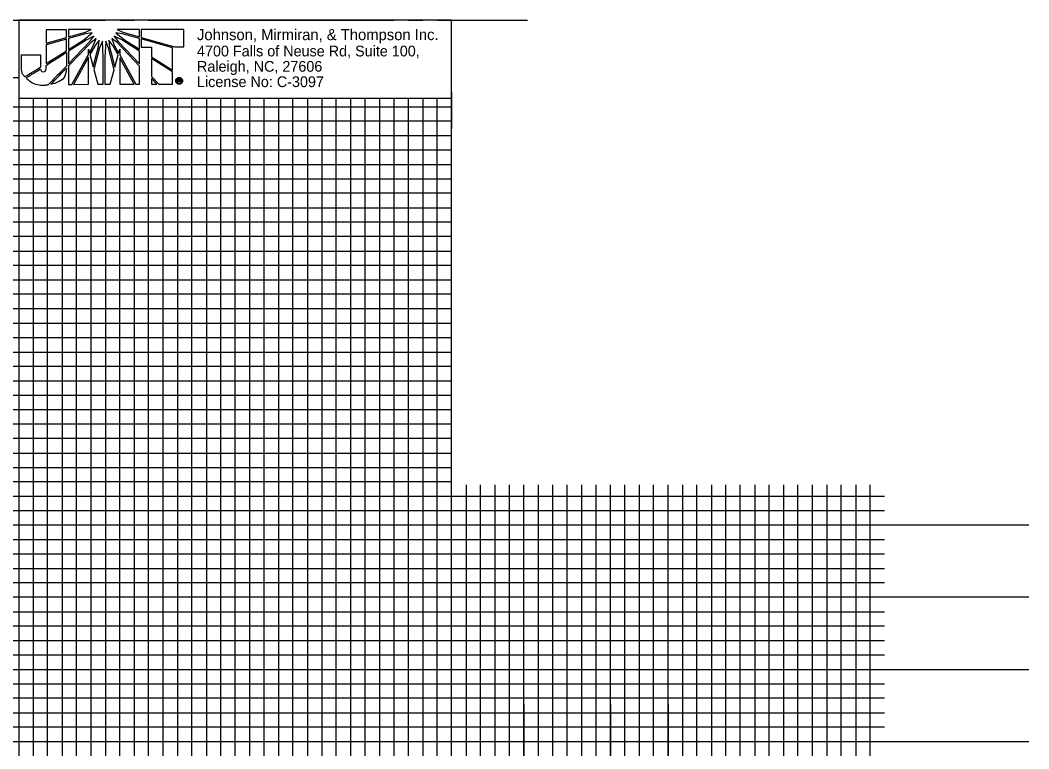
# Model space of a CAD drawing. Extents: x 1648435 to 1651603, y 802691 to 845762.
# Drawn here: x 1651253.8 to 1651603.3, y 845509.5 to 845762 of the extents above; entities that cross this region are included whole.
import ezdxf

# ---------------------------------------------------------------- set-up
doc = ezdxf.new("R2010")
doc.units = 0
for name, color, linetype in [('Prop Dimension Text', 7, 'Continuous'), ('Sheet Plan CELL', 7, 'Continuous'), ('Sheet Profile Grid Major CELL', 7, 'Continuous'), ('Sheet Profile Grid Middle CELL', 7, 'Continuous'), ('Sheet Profile Grid Minor CELL', 7, 'Continuous')]:
    doc.layers.add(name, color=color, linetype=linetype)

msp = doc.modelspace()

# ---------------------------------------------------------------- linework, layer by layer
at = {"layer": 'Prop Dimension Text'}
for p, q in [((1651269.85, 845758.65), (1651262.83, 845758.65)), ((1651262.83, 845758.65), (1651262.84, 845753.99)), ((1651269.85, 845755.94), (1651269.85, 845758.65)), ((1651278.48, 845758.7), (1651270.58, 845758.69)), ((1651270.58, 845758.69), (1651270.58, 845756.18)), ((1651270.58, 845756.18), (1651276.47, 845757.8)), ((1651276.47, 845757.26), (1651270.58, 845755.63)), ((1651275.85, 845755.17), (1651278.76, 845757.54)), ((1651276.47, 845757.8), (1651278.48, 845758.7)), ((1651278.76, 845757.54), (1651276.47, 845757.26)), ((1651279.34, 845756.45), (1651276.66, 845755.09)), ((1651277.99, 845754.55), (1651279.34, 845756.45)), ((1651286.41, 845756.46), (1651287.77, 845754.52)), ((1651289.12, 845755.1), (1651286.41, 845756.46)), ((1651287.03, 845757.55), (1651289.97, 845755.14)), ((1651289.19, 845757.27), (1651287.03, 845757.55)), ((1651295.2, 845758.68), (1651287.42, 845758.7)), ((1651287.42, 845758.7), (1651289.39, 845757.78)), ((1651295.2, 845755.62), (1651289.19, 845757.27)), ((1651289.39, 845757.78), (1651295.2, 845756.15)), ((1651295.2, 845756.15), (1651295.2, 845758.68)), ((1651310.5, 845758.73), (1651295.74, 845758.71)), ((1651295.74, 845758.71), (1651295.75, 845756)), ((1651310.5, 845752.68), (1651310.5, 845758.73)), ((1651262.84, 845753.99), (1651269.85, 845755.94)), ((1651269.86, 845755.43), (1651262.84, 845753.46)), ((1651262.84, 845753.46), (1651262.85, 845746.92)), ((1651269.86, 845751.37), (1651269.86, 845755.43)), ((1651270.58, 845755.63), (1651270.59, 845751.83)), ((1651270.59, 845751.83), (1651275.85, 845755.17)), ((1651276.66, 845755.09), (1651270.59, 845751.22)), ((1651270.59, 845746.84), (1651277.99, 845754.55)), ((1651278.29, 845754.17), (1651270.59, 845746.1)), ((1651277.83, 845750.68), (1651279.29, 845753.36)), ((1651279.77, 845753.2), (1651278.02, 845750.02)), ((1651280.15, 845755.61), (1651278.29, 845754.17)), ((1651279.29, 845753.36), (1651280.15, 845755.61)), ((1651281.16, 845754.98), (1651279.77, 845753.2)), ((1651280.96, 845752.82), (1651281.16, 845754.98)), ((1651282.32, 845754.67), (1651281.36, 845752.42)), ((1651282.62, 845749.13), (1651282.32, 845754.67)), ((1651283.47, 845754.67), (1651283.12, 845749.14)), ((1651284.4, 845752.43), (1651283.47, 845754.67)), ((1651284.6, 845754.98), (1651284.83, 845752.74)), ((1651285.95, 845753.2), (1651284.6, 845754.98)), ((1651285.59, 845755.61), (1651286.45, 845753.36)), ((1651287.46, 845754.18), (1651285.59, 845755.61)), ((1651287.77, 845749.92), (1651285.95, 845753.2)), ((1651286.45, 845753.36), (1651287.96, 845750.58)), ((1651295.17, 845746.05), (1651287.46, 845754.18)), ((1651287.77, 845754.52), (1651295.17, 845746.78)), ((1651295.16, 845751.28), (1651289.12, 845755.1)), ((1651289.97, 845755.14), (1651295.16, 845751.9)), ((1651295.16, 845751.9), (1651295.2, 845755.62)), ((1651295.75, 845756), (1651295.75, 845755.92)), ((1651295.75, 845755.92), (1651307.37, 845752.68)), ((1651295.75, 845755.5), (1651295.75, 845755.46)), ((1651306.62, 845752.41), (1651295.75, 845755.5)), ((1651295.75, 845755.46), (1651295.75, 845752.63)), ((1651262.85, 845746.92), (1651269.86, 845751.37)), ((1651270.59, 845751.22), (1651270.59, 845746.84)), ((1651271.76, 845739.73), (1651277.48, 845750.1)), ((1651277.48, 845750.1), (1651277.48, 845751.96)), ((1651277.48, 845751.96), (1651277.83, 845750.68)), ((1651278.02, 845750.02), (1651279.15, 845745.81)), ((1651279.15, 845745.81), (1651280.96, 845752.82)), ((1651281.36, 845752.42), (1651279.38, 845744.84)), ((1651286.42, 845744.73), (1651284.4, 845752.43)), ((1651284.83, 845752.74), (1651286.66, 845745.65)), ((1651286.66, 845745.65), (1651287.77, 845749.92)), ((1651287.96, 845750.58), (1651288.32, 845751.97)), ((1651288.32, 845751.97), (1651288.32, 845749.92)), ((1651288.32, 845749.92), (1651293.93, 845739.75)), ((1651295.17, 845746.78), (1651295.16, 845751.28)), ((1651295.75, 845752.63), (1651299.35, 845752.64)), ((1651299.35, 845752.64), (1651299.36, 845749.27)), ((1651306.63, 845744.66), (1651306.62, 845752.41)), ((1651307.37, 845752.68), (1651310.5, 845752.68)), ((1651270.59, 845746.1), (1651270.6, 845739.73)), ((1651277.48, 845749.09), (1651272.3, 845739.73)), ((1651277.54, 845739.74), (1651277.48, 845749.09)), ((1651282.63, 845739.78), (1651282.62, 845749.13)), ((1651283.12, 845749.14), (1651283.13, 845739.78)), ((1651293.35, 845739.79), (1651288.32, 845748.91)), ((1651288.32, 845748.91), (1651288.33, 845739.78)), ((1651295.17, 845739.76), (1651295.17, 845746.05)), ((1651299.36, 845749.27), (1651306.63, 845744.66)), ((1651299.36, 845748.69), (1651299.36, 845742.41)), ((1651306.63, 845744.12), (1651299.36, 845748.69)), ((1651279.38, 845744.84), (1651280.71, 845739.78)), ((1651285.07, 845739.78), (1651286.42, 845744.73)), ((1651299.36, 845742.41), (1651301.88, 845739.76)), ((1651306.64, 845739.77), (1651306.63, 845744.12)), ((1651270.6, 845739.73), (1651271.76, 845739.73)), ((1651272.3, 845739.73), (1651277.54, 845739.74)), ((1651280.71, 845739.78), (1651282.63, 845739.78)), ((1651283.13, 845739.78), (1651285.07, 845739.78)), ((1651288.33, 845739.78), (1651293.35, 845739.79)), ((1651293.93, 845739.75), (1651295.17, 845739.76)), ((1651301.18, 845739.76), (1651299.36, 845741.73)), ((1651299.36, 845741.73), (1651299.36, 845739.76)), ((1651299.36, 845739.76), (1651301.18, 845739.76)), ((1651301.88, 845739.76), (1651306.64, 845739.77)), ((1651308.48, 845740.43), (1651308.48, 845741.5)), ((1651308.48, 845741.5), (1651308.92, 845741.5)), ((1651308.73, 845740.43), (1651308.48, 845740.43)), ((1651308.92, 845741.3), (1651308.73, 845741.3)), ((1651308.73, 845741.3), (1651308.73, 845741.04)), ((1651308.73, 845741.04), (1651308.92, 845741.05)), ((1651308.92, 845740.85), (1651308.73, 845740.85)), ((1651308.73, 845740.85), (1651308.73, 845740.43)), ((1651308.92, 845742.14), (1651308.92, 845741.91)), ((1651308.92, 845741.91), (1651308.92, 845742.14)), ((1651308.92, 845741.5), (1651308.92, 845741.3)), ((1651308.92, 845741.3), (1651308.92, 845741.5)), ((1651308.92, 845741.5), (1651308.99, 845741.5)), ((1651308.95, 845741.3), (1651308.92, 845741.3)), ((1651308.92, 845741.05), (1651308.92, 845740.85)), ((1651308.92, 845740.85), (1651308.92, 845741.05)), ((1651308.92, 845741.05), (1651308.93, 845741.05)), ((1651308.93, 845740.85), (1651308.92, 845740.85)), ((1651308.92, 845740.01), (1651308.92, 845739.78)), ((1651308.92, 845739.78), (1651308.92, 845740.01)), ((1651308.92, 845740.01), (1651308.93, 845740.01)), ((1651308.93, 845739.78), (1651308.92, 845739.78))]:
    msp.add_line(p, q, dxfattribs=at)
msp.add_lwpolyline([(1651253.34, 845734.91), (1651403.3, 845734.91), (1651403.3, 845761.97), (1651253.34, 845761.97)], close=True, dxfattribs=at)
for points in [[(1651262.84, 845753.99), (1651269.85, 845755.94), (1651269.85, 845758.65), (1651262.83, 845758.65), (1651262.84, 845753.99)], [(1651276.47, 845757.8), (1651278.48, 845758.7), (1651270.58, 845758.69), (1651270.58, 845756.18), (1651276.47, 845757.8)], [(1651270.58, 845755.63), (1651270.59, 845751.83), (1651275.85, 845755.17), (1651278.76, 845757.54), (1651276.47, 845757.26), (1651270.58, 845755.63)], [(1651270.59, 845751.22), (1651270.59, 845746.84), (1651277.99, 845754.55), (1651279.34, 845756.45), (1651276.66, 845755.09), (1651270.59, 845751.22)], [(1651286.41, 845756.46), (1651287.77, 845754.52), (1651295.17, 845746.78), (1651295.16, 845751.28), (1651289.12, 845755.1), (1651286.41, 845756.46)], [(1651287.03, 845757.55), (1651289.97, 845755.14), (1651295.16, 845751.9), (1651295.2, 845755.62), (1651289.19, 845757.27), (1651287.03, 845757.55)], [(1651289.39, 845757.78), (1651295.2, 845756.15), (1651295.2, 845758.68), (1651287.42, 845758.7), (1651289.39, 845757.78)], [(1651310.5, 845758.73), (1651295.74, 845758.71), (1651295.75, 845756), (1651295.75, 845755.92), (1651307.37, 845752.68), (1651310.5, 845752.68), (1651310.5, 845758.73)], [(1651262.85, 845746.92), (1651269.86, 845751.37), (1651269.86, 845755.43), (1651262.84, 845753.46), (1651262.85, 845746.92)], [(1651280.15, 845755.61), (1651278.29, 845754.17), (1651270.59, 845746.1), (1651270.6, 845739.73), (1651271.76, 845739.73), (1651277.48, 845750.1), (1651277.48, 845751.96), (1651277.83, 845750.68), (1651279.29, 845753.36), (1651280.15, 845755.61)], [(1651281.16, 845754.98), (1651279.77, 845753.2), (1651278.02, 845750.02), (1651279.15, 845745.81), (1651280.96, 845752.82), (1651281.16, 845754.98)], [(1651281.36, 845752.42), (1651279.38, 845744.84), (1651280.71, 845739.78), (1651282.63, 845739.78), (1651282.62, 845749.13), (1651282.32, 845754.67), (1651281.36, 845752.42)], [(1651283.47, 845754.67), (1651283.12, 845749.14), (1651283.13, 845739.78), (1651285.07, 845739.78), (1651286.42, 845744.73), (1651284.4, 845752.43), (1651283.47, 845754.67)], [(1651284.6, 845754.98), (1651284.83, 845752.74), (1651286.66, 845745.65), (1651287.77, 845749.92), (1651285.95, 845753.2), (1651284.6, 845754.98)], [(1651285.59, 845755.61), (1651286.45, 845753.36), (1651287.96, 845750.58), (1651288.32, 845751.97), (1651288.32, 845749.92), (1651293.93, 845739.75), (1651295.17, 845739.76), (1651295.17, 845746.05), (1651287.46, 845754.18), (1651285.59, 845755.61)], [(1651295.75, 845755.5), (1651295.75, 845755.46), (1651295.75, 845752.63), (1651299.35, 845752.64), (1651299.36, 845749.27), (1651306.63, 845744.66), (1651306.62, 845752.41), (1651295.75, 845755.5)], [(1651272.3, 845739.73), (1651277.54, 845739.74), (1651277.48, 845749.09), (1651272.3, 845739.73)], [(1651288.33, 845739.78), (1651293.35, 845739.79), (1651288.32, 845748.91), (1651288.33, 845739.78)], [(1651299.36, 845748.69), (1651299.36, 845742.41), (1651301.88, 845739.76), (1651306.64, 845739.77), (1651306.63, 845744.12), (1651299.36, 845748.69), (1651299.36, 845748.69)], [(1651299.36, 845739.76), (1651299.36, 845739.76), (1651301.18, 845739.76), (1651299.36, 845741.73), (1651299.36, 845739.76)], [(1651309.39, 845740.68), (1651309.39, 845740.63), (1651309.4, 845740.59), (1651309.4, 845740.55), (1651309.43, 845740.43), (1651309.21, 845740.43)]]:
    msp.add_lwpolyline(points, dxfattribs=at)
for points, degree in [([(1651260.83, 845749.92), (1651260.83, 845749.92), (1651254.33, 845749.92), (1651254.33, 845749.92), (1651254.33, 845749.92), (1651254.34, 845745.85), (1651254.34, 845745.85), (1651254.34, 845745.85), (1651254.34, 845745.43), (1651254.34, 845745.43), (1651254.34, 845744.15), (1651254.76, 845743.14), (1651255.5, 845742.3), (1651255.5, 845742.3), (1651260.83, 845745.55), (1651260.83, 845745.63), (1651260.83, 845745.63), (1651260.83, 845749.92), (1651260.83, 845749.92)], 3), ([(1651261.84, 845744.08), (1651261.42, 845744.08), (1651261.07, 845744.31), (1651260.91, 845745.08), (1651260.91, 845745.08), (1651255.88, 845741.96), (1651255.88, 845741.96), (1651257.43, 845740.33), (1651259.91, 845739.36), (1651262.01, 845739.36), (1651262.55, 845739.37), (1651262.97, 845739.41), (1651263.55, 845739.53), (1651263.55, 845739.53), (1651269.86, 845746.07), (1651269.86, 845746.07), (1651269.86, 845746.07), (1651269.86, 845750.79), (1651269.86, 845750.79), (1651269.86, 845750.79), (1651262.85, 845746.32), (1651262.85, 845746.32), (1651262.85, 845744.55), (1651262.42, 845744.08), (1651261.84, 845744.08)], 3), ([(1651261.84, 845744.08), (1651261.42, 845744.08), (1651261.07, 845744.31), (1651260.91, 845745.08), (1651260.91, 845745.08), (1651255.88, 845741.96), (1651255.88, 845741.96), (1651257.43, 845740.33), (1651259.91, 845739.36), (1651262.01, 845739.36), (1651262.55, 845739.37), (1651262.97, 845739.41), (1651263.55, 845739.53), (1651263.55, 845739.53), (1651269.86, 845746.07), (1651269.86, 845746.07), (1651269.86, 845746.07), (1651269.86, 845750.79), (1651269.86, 845750.79), (1651269.86, 845750.79), (1651262.85, 845746.32), (1651262.85, 845746.32), (1651262.85, 845744.55), (1651262.42, 845744.08), (1651261.84, 845744.08)], 3), ([(1651269.86, 845745.32), (1651269.86, 845745.32), (1651264.4, 845739.68), (1651264.4, 845739.68), (1651267.08, 845740.34), (1651269.74, 845742.12), (1651269.86, 845745.32)], 3), ([(1651308.92, 845739.78), (1651308.6, 845739.78), (1651308.32, 845739.89), (1651308.08, 845740.13), (1651307.85, 845740.35), (1651307.73, 845740.63), (1651307.73, 845740.97), (1651307.73, 845741.3), (1651307.85, 845741.58), (1651308.08, 845741.8), (1651308.32, 845742.02), (1651308.59, 845742.14), (1651308.92, 845742.14)], 3), ([(1651308.92, 845741.91), (1651308.66, 845741.91), (1651308.43, 845741.82), (1651308.25, 845741.65), (1651308.06, 845741.46), (1651307.97, 845741.23), (1651307.97, 845740.97), (1651307.97, 845740.7), (1651308.06, 845740.47), (1651308.25, 845740.28), (1651308.44, 845740.1), (1651308.66, 845740.01), (1651308.92, 845740.01)], 3), ([(1651308.92, 845742.14), (1651309.25, 845742.14), (1651309.54, 845742.02), (1651309.77, 845741.8), (1651310, 845741.58), (1651310.12, 845741.3), (1651310.12, 845740.97)], 3), ([(1651308.93, 845740.01), (1651309.2, 845740.01), (1651309.42, 845740.1), (1651309.61, 845740.29), (1651309.79, 845740.47), (1651309.89, 845740.7), (1651309.89, 845740.97), (1651309.89, 845741.23), (1651309.79, 845741.47), (1651309.6, 845741.65), (1651309.42, 845741.83), (1651309.19, 845741.91), (1651308.92, 845741.91)], 3), ([(1651308.93, 845741.05), (1651309.09, 845741.05), (1651309.17, 845741.09), (1651309.17, 845741.18), (1651309.17, 845741.26), (1651309.1, 845741.3), (1651308.95, 845741.3)], 3), ([(1651310.12, 845740.97), (1651310.12, 845740.64), (1651310.01, 845740.35), (1651309.78, 845740.12), (1651309.55, 845739.89), (1651309.26, 845739.78), (1651308.93, 845739.78)], 3), ([(1651309.12, 845740.81), (1651309.09, 845740.83), (1651309.03, 845740.85), (1651308.93, 845740.85)], 2), ([(1651308.99, 845741.5), (1651309.26, 845741.5), (1651309.4, 845741.4), (1651309.4, 845741.18), (1651309.4, 845741.08), (1651309.36, 845741.01), (1651309.27, 845740.95)], 3), ([(1651309.21, 845740.43), (1651309.18, 845740.49), (1651309.16, 845740.55), (1651309.16, 845740.63), (1651309.16, 845740.72), (1651309.15, 845740.78), (1651309.12, 845740.81)], 3), ([(1651309.27, 845740.95), (1651309.34, 845740.91), (1651309.38, 845740.82), (1651309.39, 845740.68)], 2)]:
    msp.add_open_spline(points, degree=degree, dxfattribs=at)
at = {"layer": 'Sheet Plan CELL'}
msp.add_line((1651403.3, 845736.88), (1651403.3, 845724.39), dxfattribs=at)
msp.add_line((1651403.3, 845736.88), (1651403.3, 845724.39), dxfattribs=at)
at = {"layer": 'Sheet Profile Grid Major CELL'}
for points in [[(1650803.35, 845761.97), (1650853.35, 845761.97), (1650853.35, 845261.97), (1650903.35, 845261.97), (1650903.35, 845761.97), (1650953.35, 845761.97), (1650953.35, 845261.97), (1651003.35, 845261.97), (1651003.35, 845761.97), (1651053.35, 845761.97), (1651053.35, 845261.97), (1651103.35, 845261.97), (1651103.35, 845761.97), (1651153.35, 845761.97), (1651153.35, 845261.97), (1651203.35, 845261.97), (1651203.35, 845761.97), (1651253.35, 845761.97), (1651253.35, 845261.97), (1651303.35, 845261.97), (1651303.35, 845734.91)], [(1651303.35, 845761.97), (1651353.35, 845761.97)], [(1651353.35, 845734.91), (1651353.35, 845261.97), (1651403.35, 845261.97), (1651403.35, 845761.97), (1651429.65, 845761.97)], [(1650103.35, 845711.97), (1651403.35, 845711.97)], [(1651403.35, 845661.97), (1650103.35, 845661.97), (1650103.35, 845611.97), (1651403.35, 845611.97)], [(1651453.35, 845600.92), (1651453.35, 845261.97), (1651503.35, 845261.97), (1651503.35, 845261.97), (1651503.35, 845600.92)], [(1651603.35, 845561.97), (1650103.35, 845561.97), (1650103.35, 845511.97), (1651603.35, 845511.97)]]:
    msp.add_lwpolyline(points, dxfattribs=at)
at = {"layer": 'Sheet Profile Grid Middle CELL'}
for points in [[(1650828.35, 845761.97), (1650878.35, 845761.97), (1650878.35, 845261.97), (1650928.35, 845261.97), (1650928.35, 845761.97), (1650978.35, 845761.97), (1650978.35, 845261.97), (1651028.35, 845261.97), (1651028.35, 845761.97), (1651078.35, 845761.97), (1651078.35, 845261.97), (1651128.35, 845261.97), (1651128.35, 845761.97), (1651178.35, 845761.97), (1651178.35, 845261.97), (1651228.35, 845261.97), (1651228.35, 845761.97), (1651278.35, 845761.97)], [(1651328.35, 845761.97), (1651378.35, 845761.97)], [(1651278.35, 845734.91), (1651278.35, 845261.97), (1651328.35, 845261.97), (1651328.35, 845734.91)], [(1651378.35, 845734.91), (1651378.35, 845261.97), (1651428.35, 845261.97), (1651428.35, 845600.92)], [(1651403.35, 845686.97), (1650103.35, 845686.97), (1650103.35, 845636.97), (1651403.35, 845636.97)], [(1651428.35, 845524.77), (1651428.35, 845261.97), (1651478.35, 845261.97), (1651478.35, 845600.92)], [(1651478.35, 845524.77), (1651478.35, 845261.97), (1651528.35, 845261.97), (1651528.35, 845600.92)], [(1651603.35, 845586.97), (1650103.35, 845586.97), (1650103.35, 845536.97), (1651428.35, 845536.97)], [(1651428.35, 845536.97), (1651603.35, 845536.97)], [(1651428.35, 845536.97), (1651603.35, 845536.97)]]:
    msp.add_lwpolyline(points, dxfattribs=at)
at = {"layer": 'Sheet Profile Grid Minor CELL'}
for p, q in [((1651403.3, 845756.97), (1651403.35, 845756.97)), ((1651403.35, 845751.97), (1651403.3, 845751.97)), ((1651403.3, 845746.97), (1651403.35, 845746.97)), ((1651403.3, 845626.97), (1650153.35, 845626.97)), ((1651403.35, 845621.97), (1650153.35, 845621.97)), ((1651403.35, 845616.97), (1650153.35, 845616.97)), ((1650153.35, 845606.97), (1651403.35, 845606.97)), ((1651403.35, 845601.97), (1650153.35, 845601.97)), ((1650153.35, 845596.97), (1651553.35, 845596.97)), ((1651553.35, 845576.97), (1650153.35, 845576.97)), ((1650153.35, 845571.97), (1651553.35, 845571.97)), ((1651553.35, 845551.97), (1650153.35, 845551.97)), ((1650153.35, 845546.97), (1651553.35, 845546.97)), ((1651553.35, 845526.97), (1650153.35, 845526.97)), ((1650153.35, 845521.97), (1651553.35, 845521.97)), ((1651553.35, 845516.97), (1650153.35, 845516.97))]:
    msp.add_line(p, q, dxfattribs=at)
for points in [[(1651248.35, 845761.97), (1651258.35, 845761.97)], [(1651263.35, 845761.97), (1651268.35, 845761.97)], [(1651273.35, 845761.97), (1651283.35, 845761.97)], [(1651288.35, 845761.97), (1651293.35, 845761.97)], [(1651298.35, 845761.97), (1651308.35, 845761.97)], [(1651313.35, 845761.97), (1651318.35, 845761.97)], [(1651323.35, 845761.97), (1651333.35, 845761.97)], [(1651338.35, 845761.97), (1651343.35, 845761.97)], [(1651348.35, 845761.97), (1651358.35, 845761.97)], [(1651363.35, 845761.97), (1651368.35, 845761.97)], [(1651373.35, 845761.97), (1651383.35, 845761.97)], [(1651388.35, 845761.97), (1651393.35, 845761.97)], [(1651398.35, 845761.97), (1651408.35, 845761.97)], [(1651253.34, 845741.97), (1650153.35, 845741.97), (1650153.35, 845731.97), (1651403.35, 845731.97)], [(1651403.35, 845741.97), (1651403.3, 845741.97)], [(1651258.35, 845734.91), (1651258.35, 845261.97), (1651263.35, 845261.97), (1651263.35, 845734.91)], [(1651268.35, 845734.91), (1651268.35, 845261.97), (1651273.35, 845261.97), (1651273.35, 845734.91)], [(1651283.35, 845734.91), (1651283.35, 845261.97), (1651288.35, 845261.97), (1651288.35, 845734.91)], [(1651293.35, 845261.97), (1651298.35, 845261.97), (1651298.35, 845734.91)], [(1651293.35, 845734.91), (1651293.35, 845261.97)], [(1651308.35, 845734.91), (1651308.35, 845261.97), (1651313.35, 845261.97), (1651313.35, 845734.91)], [(1651318.35, 845734.91), (1651318.35, 845261.97), (1651323.35, 845261.97), (1651323.35, 845734.91)], [(1651333.35, 845734.91), (1651333.35, 845261.97), (1651338.35, 845261.97), (1651338.35, 845734.91)], [(1651343.35, 845734.91), (1651343.35, 845261.97), (1651348.35, 845261.97), (1651348.35, 845734.91)], [(1651358.35, 845734.91), (1651358.35, 845261.97), (1651363.35, 845261.97), (1651363.35, 845734.91)], [(1651368.35, 845734.91), (1651368.35, 845261.97), (1651373.35, 845261.97), (1651373.35, 845734.91)], [(1651383.35, 845734.91), (1651383.35, 845261.97), (1651388.35, 845261.97), (1651388.35, 845734.91)], [(1651393.35, 845734.91), (1651393.35, 845261.97), (1651398.35, 845261.97), (1651398.35, 845734.91)], [(1651403.3, 845726.97), (1650153.35, 845726.97), (1650153.35, 845721.97), (1651403.35, 845721.97)], [(1651403.35, 845716.97), (1650153.35, 845716.97), (1650153.35, 845706.97), (1651403.35, 845706.97)], [(1651403.35, 845701.97), (1650153.35, 845701.97), (1650153.35, 845696.97), (1651403.35, 845696.97)], [(1651403.35, 845691.97), (1650153.35, 845691.97), (1650153.35, 845681.97), (1651403.35, 845681.97)], [(1651403.35, 845676.97), (1650153.35, 845676.97), (1650153.35, 845671.97), (1651403.35, 845671.97)], [(1651403.35, 845666.97), (1650153.35, 845666.97), (1650153.35, 845656.97), (1651403.35, 845656.97)], [(1651403.35, 845651.87), (1650153.45, 845651.87), (1650153.45, 845646.97), (1651403.35, 845646.97)], [(1651403.35, 845641.97), (1650153.35, 845641.97), (1650153.35, 845631.97), (1651403.35, 845631.97)], [(1651408.35, 845600.92), (1651408.35, 845261.97), (1651413.35, 845261.97), (1651413.35, 845600.92)], [(1651418.35, 845600.92), (1651418.35, 845261.97), (1651423.35, 845261.97), (1651423.35, 845600.92)], [(1651433.35, 845600.92), (1651433.35, 845261.97), (1651433.35, 845261.97), (1651438.35, 845261.97), (1651443.35, 845261.97), (1651443.35, 845600.92)], [(1651438.35, 845600.92), (1651438.35, 845261.97)], [(1651448.34, 845600.92), (1651448.25, 845262.02), (1651453.25, 845262.02), (1651458.35, 845261.97), (1651458.35, 845600.92)], [(1651458.35, 845524.77), (1651458.35, 845261.97), (1651463.35, 845261.97), (1651463.35, 845600.92)], [(1651468.35, 845600.92), (1651468.35, 845261.97), (1651473.35, 845261.97), (1651473.35, 845600.92)], [(1651483.35, 845600.92), (1651483.35, 845261.97), (1651488.35, 845261.97), (1651488.35, 845600.92)], [(1651493.35, 845600.92), (1651493.35, 845261.97), (1651498.35, 845261.97), (1651498.35, 845600.92)], [(1651508.35, 845600.92), (1651508.35, 845261.97), (1651513.35, 845261.97), (1651513.35, 845600.92)], [(1651518.35, 845600.92), (1651518.35, 845261.97), (1651523.35, 845261.97), (1651523.35, 845600.92)], [(1651533.35, 845600.92), (1651533.35, 845261.97), (1651538.35, 845261.97), (1651538.35, 845600.92)], [(1651543.35, 845600.92), (1651543.35, 845261.97), (1651548.35, 845261.97), (1651548.35, 845600.92)], [(1651553.35, 845591.97), (1650153.35, 845591.97), (1650153.35, 845581.97), (1651553.35, 845581.97)], [(1651553.35, 845566.97), (1650153.35, 845566.97), (1650153.35, 845556.97), (1651553.35, 845556.97)], [(1651553.35, 845541.97), (1650153.35, 845541.97), (1650153.35, 845531.97), (1651553.35, 845531.97)]]:
    msp.add_lwpolyline(points, dxfattribs=at)

# ---------------------------------------------------------------- texts
at = {"layer": 'Prop Dimension Text'}
for s, height, p in [('Johnson, Mirmiran, & Thompson Inc.', 3.8315, (1651315.1, 845755.04)), ('4700 Falls of Neuse Rd, Suite 100, ', 3.722, (1651315.1, 845749.41)), ('Raleigh, NC, 27606', 3.722, (1651315.1, 845744.1)), ('License No: C-3097', 3.722, (1651315.1, 845738.78))]:
    msp.add_text(s, height=height, rotation=360, dxfattribs=at).set_placement(p)

doc.saveas('drawing.dxf')
